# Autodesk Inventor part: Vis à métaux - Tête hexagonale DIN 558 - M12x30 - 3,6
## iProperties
Created: 2002-09
Part Number: Vis à métaux - Tête hexagonale DIN 558 - M12x30 - 3,6
Material: Par défaut
Catalog Web Link: www.traceparts.com
Description: Vis à métaux - Tête hexagonale DIN 558 - M12x30 - 3,6
Document SubType Name: Modélisation
Designer: Maison
Control State: 0
Master: False
Checked Out: False
Shininess: 20.0
Length Units: 11269
Angle Units: 11279
Time Units: 11290
Mass Units: 11283
Length Display Precision: 3
Angle Display Precision: 2
Density: 0.0
Volumn: 0.0
Area: 0.0
PropertySet Name: Model Information
Author: Maison
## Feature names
1. Base1
